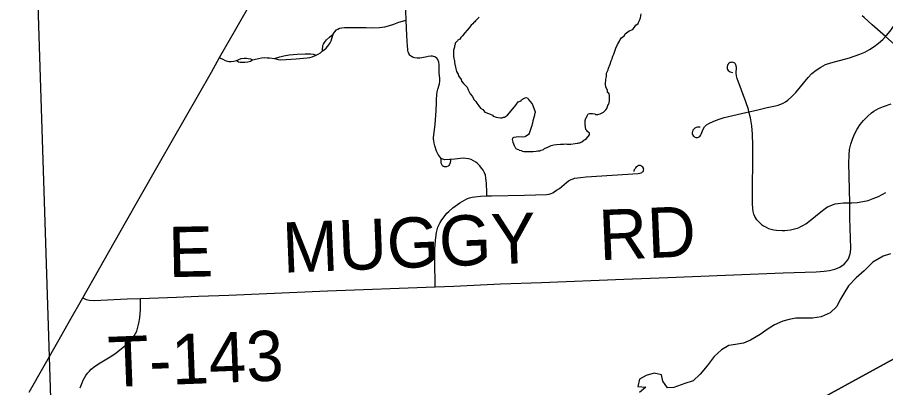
# Model space of a CAD drawing. Extents: x 63.4 to 97.4, y 0.4 to 22.4.
# Drawn here: x 67.874 to 68.856, y 18.029 to 18.448 of the extents above; entities that cross this region are included whole.
import ezdxf

# ---------------------------------------------------------------- set-up
doc = ezdxf.new("R2010")
doc.units = 0
for name, color, linetype in [('GM_X_County_Road', 7, 'Continuous'), ('GM_X_Minor_River', 7, 'Continuous'), ('GM_X_Section', 7, 'Continuous'), ('GM_X_State_Route', 7, 'Continuous'), ('GM_X_Township_Road', 7, 'Continuous'), ('GM_X_Township_Road_Text', 7, 'Continuous')]:
    doc.layers.add(name, color=color, linetype=linetype)

msp = doc.modelspace()

# ---------------------------------------------------------------- linework, layer by layer
at = {"layer": 'GM_X_County_Road'}
for points in [[(68.14823, 17.66929), (69.05133, 18.16366)], [(69.05133, 18.16366), (68.14823, 17.66929)]]:
    msp.add_lwpolyline(points, dxfattribs=at)
at = {"layer": 'GM_X_Minor_River'}
for points in [[(68.51919, 18.33874), (68.52071, 18.3391), (68.52412, 18.33905), (68.52677, 18.33863), (68.52752, 18.33786), (68.53017, 18.33783), (68.53284, 18.33855), (68.53666, 18.34039), (68.53935, 18.34301), (68.54051, 18.34452), (68.54209, 18.34905), (68.54248, 18.34943), (68.54329, 18.35321), (68.54338, 18.35929), (68.54303, 18.36119), (68.54229, 18.36234), (68.54116, 18.36274), (68.54119, 18.36502), (68.53935, 18.36922), (68.53901, 18.37189), (68.5391, 18.37796), (68.53991, 18.38099), (68.53996, 18.38441), (68.54191, 18.38818), (68.54231, 18.39007), (68.54428, 18.3946), (68.54547, 18.39839), (68.54626, 18.40065), (68.54667, 18.40255), (68.54706, 18.40368), (68.54823, 18.40594), (68.54942, 18.40935), (68.55061, 18.41275), (68.55257, 18.4169), (68.5549, 18.42066), (68.55531, 18.42256), (68.55685, 18.42444), (68.5603, 18.42705), (68.56109, 18.42893), (68.56568, 18.43229), (68.56988, 18.43413), (68.57337, 18.43901), (68.57567, 18.44088), (68.57607, 18.44202), (68.57724, 18.44428), (68.57842, 18.4473), (68.57924, 18.45185)], [(68.39604, 18.44797), (68.39181, 18.44386), (68.39103, 18.44273), (68.38988, 18.44198), (68.38872, 18.44048), (68.38718, 18.43898), (68.38487, 18.43598), (68.38255, 18.43335), (68.37985, 18.43035), (68.37715, 18.42697), (68.37523, 18.4251), (68.37406, 18.42321), (68.37176, 18.42173), (68.37137, 18.42097), (68.3706, 18.41984), (68.36906, 18.41835), (68.36904, 18.41683), (68.36826, 18.41532), (68.36823, 18.4138), (68.36705, 18.41078), (68.36695, 18.40394), (68.36729, 18.40128), (68.36765, 18.39975), (68.36802, 18.39899), (68.36798, 18.39671), (68.36977, 18.38947), (68.37049, 18.38642), (68.3716, 18.38451), (68.37234, 18.38335), (68.37269, 18.38145), (68.37567, 18.37761), (68.37602, 18.37571)], [(68.37602, 18.37571), (68.37825, 18.37302), (68.38236, 18.36878), (68.38346, 18.36573), (68.38604, 18.36113), (68.38865, 18.35805), (68.39012, 18.355), (68.39237, 18.35269), (68.39347, 18.35077), (68.3957, 18.3477), (68.39756, 18.34501), (68.40019, 18.34346), (68.40242, 18.34039), (68.40771, 18.33879), (68.4111, 18.33723), (68.41184, 18.33608), (68.41523, 18.33489), (68.4175, 18.33448), (68.42015, 18.33406), (68.42205, 18.33403), (68.42358, 18.33477), (68.42471, 18.33476), (68.42816, 18.33699), (68.4324, 18.34186), (68.43742, 18.34825), (68.44013, 18.35201), (68.44357, 18.35348), (68.44396, 18.35462), (68.44626, 18.3561), (68.44931, 18.3572), (68.45082, 18.3568), (68.45156, 18.35527), (68.45342, 18.35296), (68.45603, 18.34989), (68.45785, 18.34492), (68.45931, 18.34073), (68.45929, 18.33959), (68.45891, 18.33959), (68.4581, 18.3358), (68.45689, 18.33088), (68.45647, 18.32823), (68.45527, 18.32445), (68.4525, 18.31651), (68.45173, 18.31538), (68.4502, 18.31426), (68.44828, 18.31315), (68.44752, 18.31278), (68.44524, 18.31244), (68.44069, 18.3125), (68.43537, 18.31182), (68.43384, 18.31108), (68.43344, 18.30956), (68.43416, 18.30651), (68.43562, 18.30269), (68.43635, 18.30117), (68.43673, 18.30078), (68.43747, 18.29963), (68.43897, 18.29885), (68.44086, 18.29844), (68.44123, 18.29768), (68.44388, 18.29726), (68.44463, 18.29649), (68.44652, 18.29609), (68.45182, 18.29601), (68.45296, 18.29599), (68.45713, 18.29594), (68.46055, 18.29627), (68.46245, 18.29662), (68.46473, 18.29697), (68.46626, 18.29771), (68.46892, 18.29843), (68.47008, 18.29955), (68.47427, 18.30139), (68.47733, 18.30287), (68.48038, 18.30358), (68.48341, 18.30392), (68.48797, 18.30423), (68.49138, 18.30419), (68.49366, 18.30454), (68.49556, 18.30451), (68.49973, 18.30445), (68.50466, 18.30514), (68.5077, 18.30548), (68.50885, 18.30584), (68.50998, 18.30582), (68.51228, 18.30693), (68.51458, 18.3088), (68.51573, 18.30954), (68.51726, 18.31066), (68.52073, 18.31479), (68.52076, 18.31669), (68.51889, 18.31823), (68.51852, 18.31862), (68.51777, 18.31977), (68.51665, 18.32092), (68.51598, 18.32663), (68.51605, 18.33119), (68.51684, 18.33384), (68.51723, 18.33459), (68.51802, 18.33648), (68.51919, 18.33874)], [(68.86122, 18.18046), (68.85288, 18.17776), (68.84115, 18.17086), (68.83132, 18.16131), (68.82225, 18.15328), (68.81357, 18.14412), (68.8083, 18.13535), (68.80378, 18.12811), (68.8004, 18.12087), (68.79284, 18.11361), (68.78262, 18.109), (68.77313, 18.10781), (68.75415, 18.10772), (68.74656, 18.10617), (68.73936, 18.10423), (68.72989, 18.10001), (68.72156, 18.09502), (68.71362, 18.08929), (68.70302, 18.08277), (68.69506, 18.07931), (68.68596, 18.07775), (68.67837, 18.07657), (68.67004, 18.07197), (68.66173, 18.06433), (68.65381, 18.05365), (68.64589, 18.04449), (68.63795, 18.03685), (68.62848, 18.03376), (68.61635, 18.02915), (68.60914, 18.02873), (68.60378, 18.03631), (68.60223, 18.04352), (68.59387, 18.04538), (68.58477, 18.04268), (68.5772, 18.03884), (68.57534, 18.03047), (68.58445, 18.02976), (68.57727, 18.02364)], [(68.86122, 18.18046), (68.85288, 18.17776), (68.84115, 18.17086), (68.83132, 18.16131), (68.82225, 18.15328), (68.81357, 18.14412), (68.8083, 18.13535), (68.80378, 18.12811), (68.8004, 18.12087), (68.79284, 18.11361), (68.78262, 18.109), (68.77313, 18.10781), (68.75415, 18.10772), (68.74656, 18.10617), (68.73936, 18.10423), (68.72989, 18.10001), (68.72156, 18.09502), (68.71362, 18.08929), (68.70302, 18.08277), (68.69506, 18.07931), (68.68596, 18.07775), (68.67837, 18.07657), (68.67004, 18.07197), (68.66173, 18.06433), (68.65381, 18.05365), (68.64589, 18.04449), (68.63795, 18.03685), (68.62848, 18.03376), (68.61635, 18.02915), (68.60914, 18.02873), (68.60378, 18.03631), (68.60223, 18.04352), (68.59387, 18.04538), (68.58477, 18.04268), (68.5772, 18.03884), (68.57534, 18.03047), (68.58445, 18.02976), (68.57727, 18.02364)]]:
    msp.add_lwpolyline(points, dxfattribs=at)
at = {"layer": 'GM_X_Section'}
msp.add_lwpolyline([(67.89376, 18.5672), (67.92566, 17.57266), (67.71099, 17.57298), (67.72391, 18.56172)], close=True, dxfattribs=at)
at = {"layer": 'GM_X_State_Route'}
msp.add_lwpolyline([(67.88737, 18.02391), (67.92098, 18.08345), (67.93329, 18.10504), (67.94774, 18.13055), (67.99609, 18.21592), (68.01154, 18.24287), (68.03465, 18.28336), (68.06398, 18.33462), (68.09332, 18.38584), (68.10261, 18.40225), (68.12089, 18.43452), (68.15793, 18.49925)], dxfattribs=at)
at = {"layer": 'GM_X_Township_Road'}
for points in [[(68.31344, 18.44462), (68.31295, 18.45516), (68.31272, 18.46163), (68.31262, 18.46644), (68.31267, 18.46778)], [(68.8555, 18.42586), (68.84059, 18.43911), (68.83142, 18.44746), (68.82903, 18.44943)], [(68.23079, 18.42878), (68.23252, 18.4311), (68.23464, 18.43341), (68.23618, 18.43446), (68.23811, 18.43533), (68.24071, 18.43584), (68.2438, 18.43614), (68.25319, 18.43627), (68.26816, 18.4361), (68.27471, 18.43591), (68.28338, 18.43611), (68.28627, 18.43642), (68.28945, 18.43697), (68.29368, 18.43823), (68.29946, 18.44015), (68.30537, 18.44213), (68.31344, 18.44462)], [(68.31779, 18.40502), (68.31659, 18.40691), (68.31592, 18.40855), (68.31556, 18.4101), (68.31535, 18.41174), (68.3151, 18.41498), (68.3143, 18.42729), (68.31344, 18.44462)], [(68.8555, 18.42586), (68.85682, 18.42721), (68.86075, 18.43205), (68.86969, 18.44482)], [(68.21885, 18.41), (68.22087, 18.41106), (68.22289, 18.41298), (68.22621, 18.41679), (68.22761, 18.41876), (68.22858, 18.42098), (68.22963, 18.42396), (68.23079, 18.42878)], [(68.21885, 18.41), (68.21895, 18.41221), (68.21914, 18.41482), (68.21942, 18.41597), (68.21991, 18.41732), (68.22116, 18.41925), (68.22222, 18.42088), (68.22328, 18.42214), (68.22665, 18.42541), (68.23079, 18.42878)], [(68.7011, 18.34077), (68.70982, 18.3426), (68.72185, 18.34574), (68.73102, 18.3476), (68.73404, 18.3484), (68.73698, 18.34944), (68.73979, 18.35077), (68.74247, 18.35235), (68.74502, 18.35415), (68.74975, 18.3582), (68.75406, 18.36271), (68.76795, 18.37955), (68.77228, 18.38404), (68.77707, 18.38802), (68.78226, 18.3915), (68.78499, 18.39299), (68.78783, 18.39428), (68.79373, 18.39626), (68.81462, 18.40208), (68.82644, 18.40591), (68.83216, 18.40838), (68.8376, 18.41143), (68.8428, 18.41487), (68.84777, 18.41864), (68.85245, 18.42276), (68.8555, 18.42586)], [(68.90488, 18.38164), (68.89613, 18.38965), (68.87531, 18.4082), (68.8555, 18.42586)], [(68.21163, 18.40499), (68.21394, 18.40615), (68.21649, 18.40774), (68.21885, 18.41)], [(68.10261, 18.40225), (68.10372, 18.40164), (68.10607, 18.40035), (68.10867, 18.39892), (68.11006, 18.39842), (68.1129, 18.39793), (68.11578, 18.39787), (68.11866, 18.39821), (68.12147, 18.39883)], [(68.12147, 18.39883), (68.12418, 18.39997), (68.12687, 18.40113), (68.13024, 18.40161), (68.13304, 18.40161), (68.13488, 18.40132), (68.13747, 18.40064), (68.13978, 18.39978)], [(68.12147, 18.39883), (68.12379, 18.39747), (68.12571, 18.39711), (68.12753, 18.39695), (68.13111, 18.39689), (68.13458, 18.39727), (68.13747, 18.39814), (68.13978, 18.39978)], [(68.13978, 18.39978), (68.14999, 18.4018), (68.15345, 18.40219), (68.15624, 18.40209), (68.15912, 18.4019), (68.16447, 18.40123)], [(68.16447, 18.40123), (68.17079, 18.40315), (68.17512, 18.40431), (68.18138, 18.40518), (68.19018, 18.40593), (68.1992, 18.40663), (68.20524, 18.40663), (68.20883, 18.40595), (68.21163, 18.40499)], [(68.16447, 18.40123), (68.1688, 18.40005), (68.1718, 18.3998), (68.17778, 18.39995), (68.18899, 18.40094), (68.20142, 18.4019), (68.2044, 18.40239), (68.2071, 18.40316), (68.21163, 18.40499)], [(68.35326, 18.28799), (68.35085, 18.2911), (68.34978, 18.29276), (68.34795, 18.29661), (68.34582, 18.30243), (68.34505, 18.30542), (68.34461, 18.30846), (68.34448, 18.30975), (68.34455, 18.31156), (68.34619, 18.32697), (68.34736, 18.34195), (68.34791, 18.35126), (68.34788, 18.35436), (68.34825, 18.36054), (68.34871, 18.36359), (68.34938, 18.36661), (68.35103, 18.37259), (68.35157, 18.37563), (68.35163, 18.37687), (68.35164, 18.37869), (68.35084, 18.38484), (68.35063, 18.38792), (68.3507, 18.39413), (68.35027, 18.39721), (68.34971, 18.39893), (68.34914, 18.40009), (68.34821, 18.40146), (68.34721, 18.40241), (68.34586, 18.40308), (68.34449, 18.40362), (68.34316, 18.40381), (68.34138, 18.40379), (68.3383, 18.40335), (68.33524, 18.40272), (68.32912, 18.40169), (68.32603, 18.40157), (68.32298, 18.40193), (68.32123, 18.40244), (68.32012, 18.403), (68.31935, 18.40343), (68.31849, 18.40417), (68.31779, 18.40502)], [(68.7011, 18.34077), (68.70046, 18.34338), (68.69761, 18.35233), (68.68775, 18.37866), (68.68694, 18.38164), (68.68665, 18.38471), (68.68712, 18.39107), (68.6868, 18.39286), (68.6864, 18.39402), (68.6855, 18.39537), (68.68504, 18.39579), (68.68452, 18.39614), (68.68327, 18.39662), (68.68197, 18.39686), (68.6809, 18.39681), (68.67993, 18.39658), (68.67858, 18.39586), (68.67807, 18.39542), (68.67755, 18.39481), (68.67675, 18.39347), (68.6764, 18.39198), (68.67635, 18.39047), (68.67649, 18.38966), (68.67686, 18.38882), (68.67774, 18.38761), (68.67877, 18.38669), (68.67988, 18.38613), (68.68234, 18.38552)], [(68.81506, 18.23812), (68.81422, 18.28272), (68.81431, 18.292), (68.8149, 18.29815), (68.81622, 18.30419), (68.81813, 18.31008), (68.82053, 18.31579), (68.82342, 18.32126), (68.8268, 18.32643), (68.83069, 18.33124), (68.835, 18.33568), (68.83966, 18.33976), (68.84215, 18.34159), (68.84477, 18.34322), (68.84751, 18.34465), (68.85323, 18.34702), (68.86202, 18.35)], [(68.64613, 18.32359), (68.64454, 18.32359), (68.64303, 18.32344), (68.64136, 18.32301), (68.64008, 18.32236), (68.63873, 18.32141), (68.63825, 18.32086), (68.63774, 18.32005), (68.63727, 18.31874), (68.63701, 18.31728), (68.63705, 18.31647), (68.63731, 18.31542), (68.63777, 18.31442), (68.63855, 18.31345), (68.6392, 18.31286), (68.63998, 18.31244), (68.64092, 18.31205), (68.64183, 18.31191), (68.64289, 18.31195), (68.64406, 18.31224), (68.6455, 18.31311), (68.64636, 18.31403), (68.64719, 18.31546), (68.64932, 18.32142), (68.65095, 18.32398), (68.65316, 18.32607), (68.65582, 18.32771), (68.66146, 18.33041), (68.66728, 18.33265), (68.67326, 18.33442), (68.69758, 18.34), (68.7011, 18.34077)], [(68.71287, 18.21579), (68.71001, 18.21894), (68.70791, 18.22244), (68.70675, 18.22516), (68.70588, 18.22815), (68.70543, 18.23123), (68.70519, 18.23747), (68.70544, 18.30326), (68.70517, 18.3157), (68.70426, 18.32501), (68.7027, 18.33426), (68.7011, 18.34077)], [(68.3636, 18.28703), (68.36354, 18.28543), (68.36327, 18.28355), (68.36263, 18.28152), (68.36183, 18.28029), (68.36081, 18.27948), (68.35925, 18.27879), (68.35797, 18.27868), (68.35702, 18.27877), (68.35567, 18.27916), (68.35465, 18.28002), (68.3538, 18.28125), (68.35321, 18.28296), (68.35299, 18.28409), (68.35299, 18.28564), (68.35326, 18.28799)], [(68.3636, 18.28703), (68.36246, 18.28694), (68.35723, 18.28678), (68.35503, 18.2873), (68.35326, 18.28799)], [(68.40481, 18.24578), (68.40466, 18.24994), (68.40429, 18.2599), (68.40369, 18.2661), (68.40307, 18.26914), (68.40206, 18.27205), (68.40062, 18.27478), (68.39881, 18.27732), (68.39678, 18.27969), (68.39412, 18.28248), (68.39219, 18.28407), (68.38968, 18.28565), (68.38692, 18.28683), (68.38398, 18.28781), (68.3809, 18.28822), (68.37778, 18.28834), (68.37467, 18.28824), (68.36855, 18.28755), (68.3636, 18.28703)], [(68.40481, 18.24578), (68.40986, 18.24601), (68.44726, 18.24679), (68.47221, 18.24744), (68.4753, 18.24783), (68.47758, 18.24846), (68.47938, 18.24931), (68.48099, 18.25045), (68.48355, 18.25216), (68.48678, 18.25434), (68.49464, 18.26098), (68.4972, 18.26287), (68.50023, 18.26458), (68.50222, 18.26534), (68.50374, 18.26572), (68.50715, 18.26638), (68.51046, 18.26664), (68.51701, 18.26733), (68.57599, 18.27109), (68.57784, 18.27149), (68.57924, 18.27186), (68.58008, 18.27224), (68.58092, 18.27289), (68.58142, 18.27351), (68.58175, 18.27426), (68.582, 18.27516), (68.58206, 18.27593), (68.58194, 18.27664), (68.58169, 18.27736), (68.58116, 18.27823), (68.58017, 18.27919), (68.57924, 18.27981), (68.5784, 18.28012), (68.57738, 18.28025), (68.57632, 18.28009), (68.57542, 18.27975), (68.57464, 18.27928), (68.57368, 18.27857), (68.57284, 18.27761), (68.57231, 18.27692), (68.57188, 18.27611), (68.57144, 18.27528), (68.57107, 18.27419), (68.57092, 18.2735)], [(68.34641, 18.14317), (68.34627, 18.14873), (68.34581, 18.16744), (68.34602, 18.18616), (68.34653, 18.1955), (68.34725, 18.20172), (68.34773, 18.20456), (68.34839, 18.2074), (68.34934, 18.21063), (68.35199, 18.21593), (68.35379, 18.21887), (68.35742, 18.22383), (68.35949, 18.22617), (68.36169, 18.22838), (68.36643, 18.23245), (68.37402, 18.23795), (68.37935, 18.24119), (68.38217, 18.24252), (68.38509, 18.24358), (68.3881, 18.24436), (68.39118, 18.24487), (68.39739, 18.24544), (68.40481, 18.24578)], [(68.81506, 18.23812), (68.81733, 18.23817), (68.82356, 18.23858), (68.82975, 18.23943), (68.83584, 18.2408), (68.84175, 18.24277), (68.84745, 18.24533), (68.85573, 18.24972)], [(68.71287, 18.21579), (68.71519, 18.21369), (68.71773, 18.21187), (68.72044, 18.21034), (68.7233, 18.20908), (68.72627, 18.20812), (68.72931, 18.20743), (68.73241, 18.20699), (68.73864, 18.20675), (68.74175, 18.2069), (68.74795, 18.20769), (68.75407, 18.20893), (68.75703, 18.20989), (68.75989, 18.21116), (68.76263, 18.21265), (68.76526, 18.21432), (68.77028, 18.21803), (68.78237, 18.22793), (68.78733, 18.23171), (68.78998, 18.23337), (68.79277, 18.23476), (68.79568, 18.23587), (68.79869, 18.23671), (68.80175, 18.23732), (68.80796, 18.23794), (68.81506, 18.23812)], [(68.81642, 18.18677), (68.81536, 18.22086), (68.81506, 18.23812)], [(68.34641, 18.14317), (68.36732, 18.14396), (68.42008, 18.14628), (68.46664, 18.14798), (68.55974, 18.15172), (68.60939, 18.15367), (68.73975, 18.15888), (68.77702, 18.16005), (68.78625, 18.16073), (68.79232, 18.16161), (68.79824, 18.16304), (68.80108, 18.16406), (68.8038, 18.16534), (68.80886, 18.16883), (68.81155, 18.17164), (68.8135, 18.17457), (68.81484, 18.17811), (68.81582, 18.18201), (68.81642, 18.18677)], [(68.01296, 18.12991), (68.05386, 18.13147), (68.0787, 18.13245), (68.11284, 18.13357), (68.22455, 18.13856), (68.34641, 18.14317)], [(67.94493, 18.02884), (67.94705, 18.03466), (67.94833, 18.03747), (67.9498, 18.0402), (67.95143, 18.04282), (67.95326, 18.04531), (67.95528, 18.04764), (67.95746, 18.04983), (67.96227, 18.0537), (67.96742, 18.05716), (67.98069, 18.06511), (67.98576, 18.06865), (67.99553, 18.07629), (68.00014, 18.0804), (68.00232, 18.08256), (68.00421, 18.08501), (68.00592, 18.08758), (68.00748, 18.09026), (68.0088, 18.09305), (68.00987, 18.09595), (68.01135, 18.10195), (68.0123, 18.10806), (68.01296, 18.11732), (68.01299, 18.12262), (68.013, 18.12676), (68.01296, 18.12991)], [(67.94774, 18.13055), (67.95179, 18.12889), (67.95529, 18.12792), (67.96073, 18.12753), (67.998, 18.12935), (68.01296, 18.12991)]]:
    msp.add_lwpolyline(points, dxfattribs=at)

# ---------------------------------------------------------------- texts
at = {"layer": 'GM_X_Township_Road_Text'}
for s, height, rotation, p in [('RD', 0.056818, 2.46923, (68.53242, 18.17311)), ('MUGGY', 0.056818, 2.29062, (68.17458, 18.15894)), ('E', 0.05682, 1.12477, (68.045, 18.15394)), ('T-143', 0.056818, 2.22622, (67.97736, 18.0297))]:
    msp.add_text(s, height=height, rotation=rotation, dxfattribs=at).set_placement(p)

doc.saveas('drawing.dxf')
